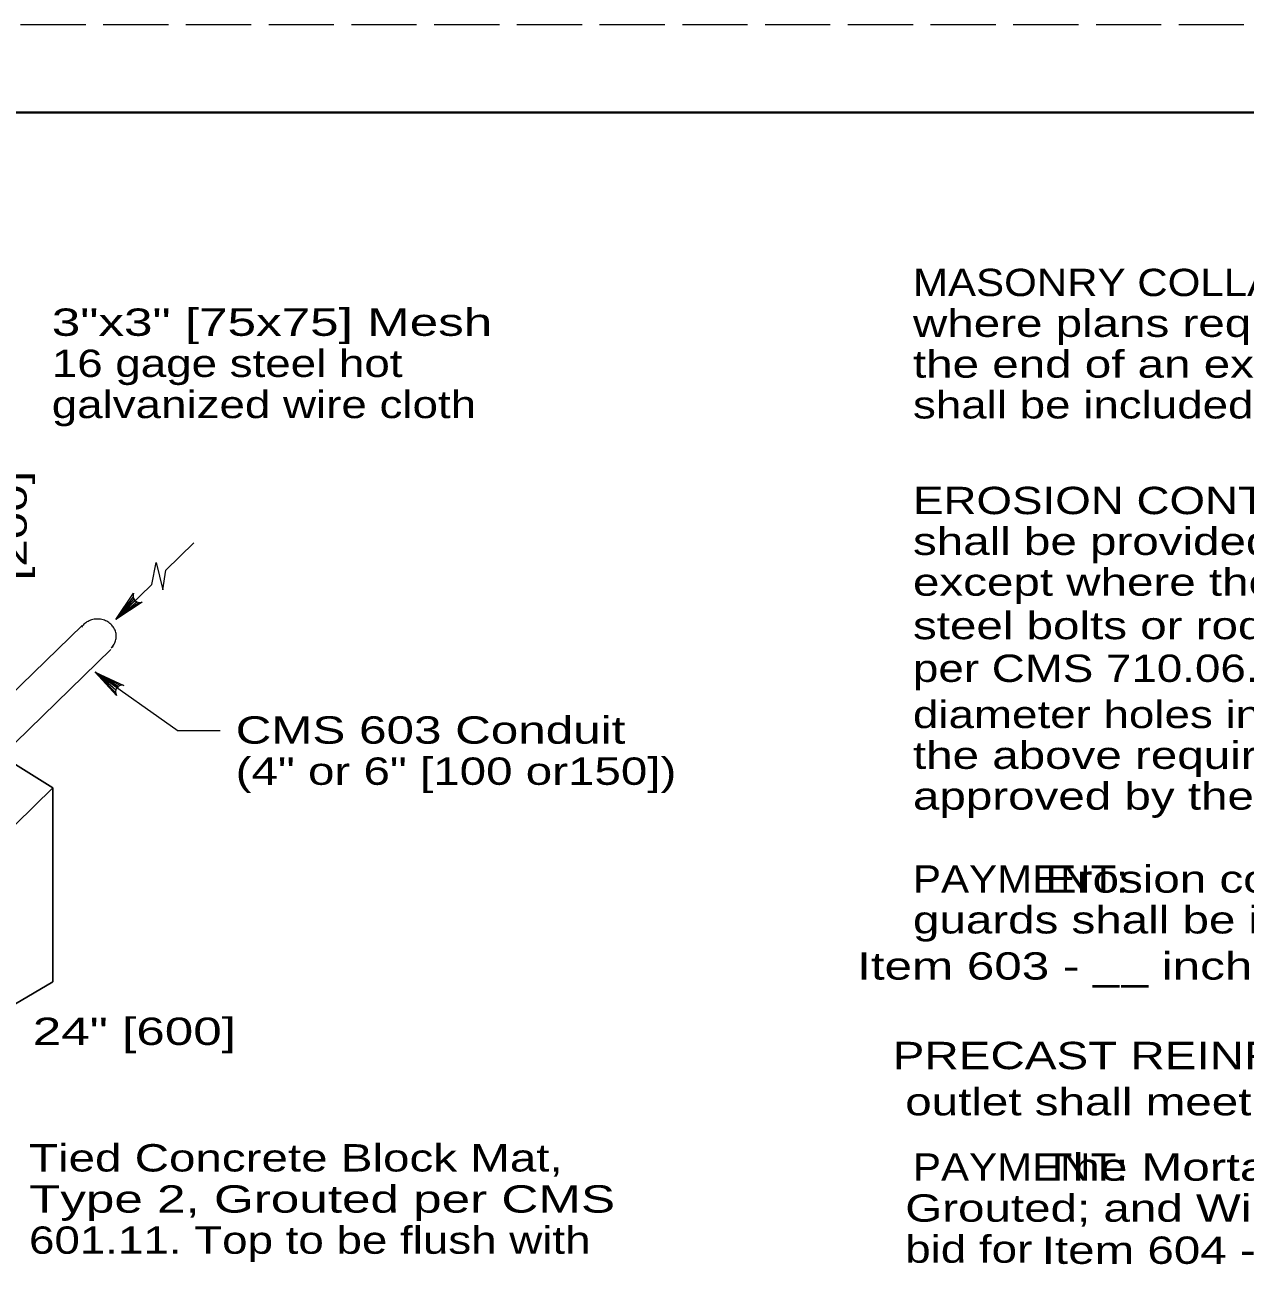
# Model space of a CAD drawing. Extents: x 1083.1 to 1117.1, y 697.4 to 741.4.
# Drawn here: x 1101.68 to 1108.64, y 734.28 to 741.35 of the extents above; entities that cross this region are included whole.
import ezdxf
from ezdxf.enums import TextEntityAlignment as Align

# ---------------------------------------------------------------- set-up
doc = ezdxf.new("R2010")
doc.units = 0
doc.header["$LTSCALE"] = 0.062
doc.linetypes.add('LONG_DASHED', pattern=[7.5, 6, -1.5])
doc.layers.add('1', color=7, linetype='Continuous', lineweight=13)

msp = doc.modelspace()

# ---------------------------------------------------------------- linework, layer by layer
at = {"layer": '1', "lineweight": 25}
for p, q in [((1085.12642, 740.85408), (1116.62642, 740.85408)), ((1101.35767, 737.30017), (1102.00192, 737.92825)), ((1101.54458, 737.18333), (1102.16675, 737.78975)), ((1101.83592, 737.00125), (1100.70367, 737.70908)), ((1099.764, 734.98167), (1101.83592, 737.00125)), ((1101.83592, 735.895), (1101.83592, 737.00125)), ((1099.764, 734.67442), (1101.83592, 735.895))]:
    msp.add_line(p, q, dxfattribs=at)
at = {"layer": '1'}
for p, q in [((1102.48067, 738.24275), (1102.63883, 738.39992)), ((1102.19442, 737.96233), (1102.399, 738.16175)), ((1102.29283, 738.09083), (1102.19442, 737.96233)), ((1102.29675, 738.07908), (1102.19442, 737.96233)), ((1102.3035, 738.06992), (1102.19442, 737.96233)), ((1102.31558, 738.06167), (1102.19442, 737.96233)), ((1102.32725, 738.05858), (1102.19442, 737.96233)), ((1102.20925, 737.56833), (1102.07675, 737.66133)), ((1102.20067, 737.57133), (1102.07675, 737.66133)), ((1102.1945, 737.55808), (1102.07675, 737.66133)), ((1102.19333, 737.54608), (1102.07675, 737.66133)), ((1102.20867, 737.57958), (1102.07675, 737.66133)), ((1102.21958, 737.58533), (1102.07675, 737.66133)), ((1102.07675, 737.66133), (1102.5505, 737.32717)), ((1102.78958, 737.32717), (1102.5505, 737.32717))]:
    msp.add_line(p, q, dxfattribs=at)
at = {"layer": '1', "linetype": 'LONG_DASHED'}
msp.add_lwpolyline([(1083.12642, 719.35408), (1117.12642, 719.35408), (1117.12642, 741.35408), (1083.12642, 741.35408)], close=True, dxfattribs=at)
at = {"layer": '1', "lineweight": 40}
msp.add_lwpolyline([(1085.12642, 740.85408), (1116.62642, 740.85408), (1116.62642, 719.85408), (1085.12642, 719.85408)], close=True, dxfattribs=at)
msp.add_lwpolyline([(1085.12642, 740.85408), (1116.62642, 740.85408), (1116.62642, 719.85408), (1085.12642, 719.85408)], close=True, dxfattribs=at)
at = {"layer": '1'}
for points in [[(1102.399, 738.16175), (1102.42392, 738.28783), (1102.46225, 738.131), (1102.48067, 738.24275)], [(1102.34533, 738.06142), (1102.19442, 737.96233), (1102.29558, 738.11183)], [(1102.19917, 737.52875), (1102.07675, 737.66133), (1102.24075, 737.586)]]:
    msp.add_lwpolyline(points, dxfattribs=at)
for centre, start, end in [((1102.33063, 738.09669), 156.6806, 292.50672), ((1102.23152, 737.54899), 76.09768, 211.92381)]:
    msp.add_arc(centre, 0.0382, start, end, dxfattribs=at)
for centre, major_axis, start_param, end_param in [((1102.07636, 737.86013), (0, 0.09981), 0.8014785, 0.9459716), ((1102.08038, 737.85615), (0, 0.10558), 0.6652989, 0.8019337), ((1102.0838, 737.85149), (0, 0.11145), 0.530592, 0.6646977), ((1102.08657, 737.84666), (0, 0.11707), 0.403277, 0.5309657), ((1102.08834, 737.84222), (0, 0.12188), 0.2769437, 0.4028861), ((1102.08934, 737.83869), (0, 0.12556), 0.1550055, 0.2772713), ((1102.08963, 737.83657), (0, 0.12771), 0.0331609, 0.1547235), ((1102.08968, 737.83609), (0, 0.12819), 6.1955651, 6.3166721), ((1102.08975, 737.83732), (0, 0.12695), 6.0737692, 6.1952758), ((1102.09036, 737.84013), (0, 0.12407), 5.9497711, 6.0740911), ((1102.09165, 737.84412), (0, 0.11986), 5.8236144, 5.9494089), ((1102.09392, 737.84881), (0, 0.11461), 5.6924557, 5.8239963), ((1102.09696, 737.85364), (0, 0.10884), 5.5580004, 5.6918984), ((1102.10076, 737.85803), (0, 0.10293), 5.4169322, 5.5584851), ((1102.10472, 737.86166), (0, 0.09742), 5.2716627, 5.4159481), ((1102.10865, 737.86415), (0, 0.09263), 5.1206362, 5.2723474), ((1102.10929, 737.86829), (0, 0.09184), 4.1833124, 4.3336775), ((1102.11185, 737.86573), (0, 0.08895), 4.9653342, 5.1192262), ((1102.1124, 737.86706), (0, 0.08838), 4.3330187, 4.4892472), ((1102.11408, 737.86626), (0, 0.08657), 4.8079957, 4.9660933), ((1102.11433, 737.86647), (0, 0.08628), 4.4907706, 4.6483291), ((1102.11493, 737.86649), (0, 0.08566), 4.6476024, 4.8062871), ((1102.10556, 737.87069), (0, 0.09641), 4.0343058, 4.1821344)]:
    msp.add_ellipse(centre, major_axis=major_axis, ratio=0.96, start_param=start_param, end_param=end_param, dxfattribs=at)
at = {"layer": '1', "lineweight": 25}
msp.add_ellipse((1102.10146, 737.87406), major_axis=(0, 0.10185), ratio=0.96, start_param=3.8948907, end_param=4.0348655, dxfattribs=at)

# ---------------------------------------------------------------- texts
at = {"layer": '1'}
for s, width, p in [('MASONRY COLLARS:', 1.15, (1106.74217, 739.8065)), ('3"x3" [75x75] Mesh', 1.4, (1101.82917, 739.57983)), ('where plans require that a pipe extension be joined to', 1.3, (1106.74217, 739.57383)), ('16 gage steel hot', 1.25, (1101.82917, 739.34517)), ('the end of an existing pipe with a butt joint.  The cost', 1.3, (1106.74217, 739.34117)), ('galvanized wire cloth', 1.25, (1101.82917, 739.1105)), ('shall be included in the unit price bid for the new conduit.', 1.25, (1106.74217, 739.10842)), ('EROSION CONTROL PAD AND ANIMAL GUARDS:', 1.25, (1106.74217, 738.56275)), ('shall be provided at the outlet end of all farm drains', 1.3, (1106.74217, 738.33008)), ('except where they outlet into a drainage structure.  The', 1.3, (1106.74217, 738.09733)), ('steel bolts or rods for the animal guard shall be galvanized', 1.3, (1106.74217, 737.8495)), ('per CMS 710.06.  In lieu of drilling or punching the 1/2" [13]', 1.25, (1106.74217, 737.60567)), ('diameter holes into the pipe, a metal collar meeting all of', 1.25, (1106.74217, 737.34242)), ('CMS 603 Conduit', 1.35, (1102.87817, 737.25333)), ('the above requirements may be clamped onto the pipe if ', 1.3, (1106.74217, 737.10975)), ('(4" or 6" [100 or150])', 1.3, (1102.87817, 737.01867)), ('approved by the Engineer.', 1.3, (1106.74217, 736.87708)), ('PAYMENT:', 1.15, (1106.74217, 736.4035)), ('          Erosion control pads, masonry collars, and animal', 1.3, (1106.74217, 736.4035)), ('guards shall be included in the unit price bid for', 1.3, (1106.74217, 736.17083)), ('    Item 603 - __ inch [mm] Conduit, Type __ .', 1.35, (1106.1105, 735.9075)), ('24" [600]', 1.4, (1101.72058, 735.53475)), ('outlet shall meet the requirements of CMS 604.', 1.3, (1106.698, 735.13333)), ('Tied Concrete Block Mat, ', 1.3, (1101.69925, 734.813)), ('PAYMENT:', 1.15, (1106.74217, 734.76033)), ('          The Mortar; Tied Concrete Block Mat, Type 2, ', 1.35, (1106.698, 734.76058)), ('Type 2, Grouted per CMS ', 1.4, (1101.69925, 734.57833)), ('Grouted; and Wire Mesh shall be included in the unit price ', 1.3, (1106.698, 734.52658)), ('601.11. Top to be flush with ', 1.25, (1101.69925, 734.34367)), ('bid for', 1.25, (1106.698, 734.29258)), ('    Item 604 - Precast Reinforced Concrete Outlet.', 1.3, (1107.17525, 734.28608))]:
    msp.add_text(s, height=0.156, dxfattribs=dict(at, width=width)).set_placement(p)
at = {"layer": '1', "width": 1.35}
msp.add_text('[200]', height=0.156, rotation=90, dxfattribs=at).set_placement((1101.68617, 738.49758), align=Align.CENTER)
at = {"layer": '1', "width": 1.3}
msp.add_text('PRECAST REINFORCED CONCRETE OUTLET:', height=0.156, dxfattribs=at).set_placement((1109.60979, 735.39675), align=Align.CENTER)

doc.saveas('drawing.dxf')
